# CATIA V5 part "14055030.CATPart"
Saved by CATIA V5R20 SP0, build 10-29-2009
Part number: 14055030
Definition: NONE
Nomenclature: 14055030
Source: Unknown
Description: 14055030
Bounding box of the stored display mesh (mm): x -15 to 60, y -41.5 to 31.6, z -31.6 to 31.6
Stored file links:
  C:\Users\Utente\Desktop\IO LAVORO\3D X SITO CF\X SITO\PLASTICA\RF2\14055030.CATPart
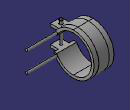
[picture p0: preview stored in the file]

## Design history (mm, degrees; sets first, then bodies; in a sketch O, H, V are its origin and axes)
Body1 "14055030" (main body)
  Solid1: solid without history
